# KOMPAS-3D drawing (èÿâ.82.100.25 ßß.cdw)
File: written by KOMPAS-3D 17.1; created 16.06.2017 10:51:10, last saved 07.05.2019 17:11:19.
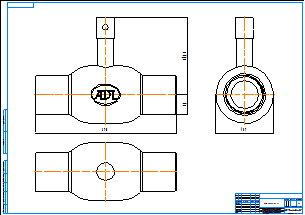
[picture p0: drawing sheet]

Sheet 1: A1, landscape

Title block, sheet 1: name: КШГ.82.100.25 сс; material: Внимание! Данный продукт является объектом авторского права ООО «Торговый Дом АДЛ». / Запрещается изменение, копирование, распространение / (в том числе путем копирования на другие сайты и ресурсы в Интернете) / или любое иное использование информации и объектов без предварительного / согласия правообладателя (ООО «Торговый Дом АДЛ»).; scale: 1:1; sheets: 1; organisation: ООО "Торговый дом АДЛ"; sheet format: A1; stored path: C:\Users\tra\Desktop\2д чертежи\Шаровые краны БИВАЛ\КШ_Бивал_серия_82_85\KOMPAS 2D\КШГ.82.100.25 сс.cdw

Views: Спереди 1, Проекционный вид 2, Проекционный вид 3
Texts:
  Klimkovich
  ADL
Dimensions and other numbers on the sheet: 390; 214,6; 54; 159; 1:1; 1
